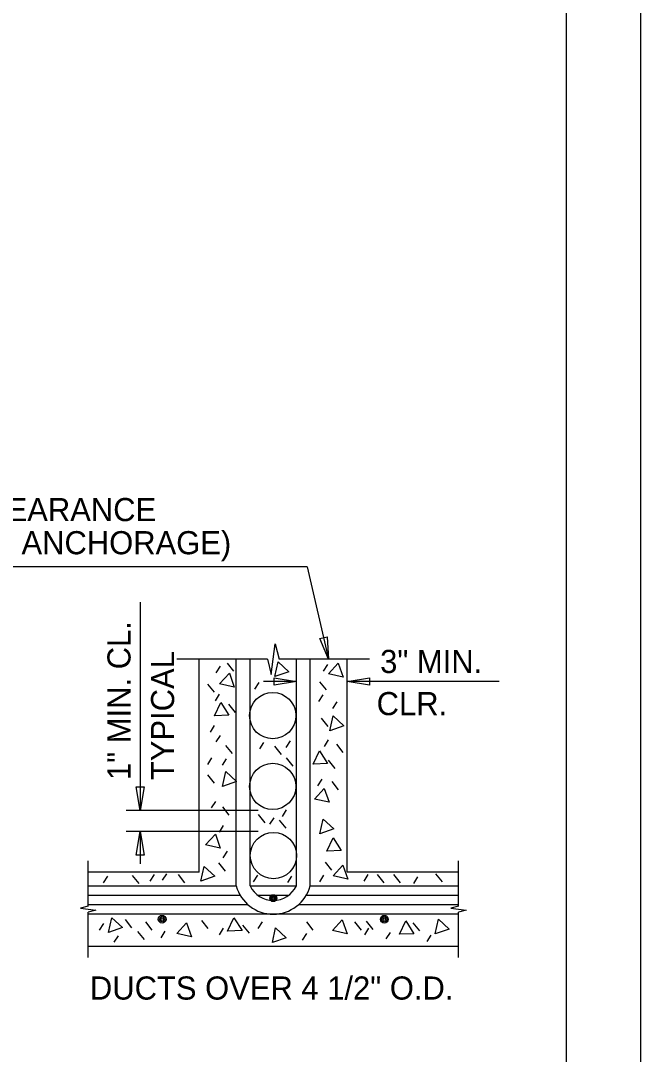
# Model space of a CAD drawing. Extents: x 0 to 22.7, y 0 to 15.7.
# Drawn here: x 19.878 to 22.667, y 4.569 to 9.222 of the extents above; entities that cross this region are included whole.
import ezdxf

# ---------------------------------------------------------------- set-up
doc = ezdxf.new("R2010")
doc.units = 0
for name, color, linetype in [('BORDER_ANNO_Cutsheet', 7, 'Continuous'), ('BRDG_ANNO_Anno-Sheet', 7, 'Continuous'), ('BRDG_ANNO_General-Notes', 7, 'Continuous'), ('BRDG_BASE_Obj-Line', 7, 'Continuous'), ('BRDG_BASE_Pattern', 7, 'Continuous'), ('BRDG_BASE_Rebar', 7, 'Continuous')]:
    doc.layers.add(name, color=color, linetype=linetype)

msp = doc.modelspace()

# ---------------------------------------------------------------- linework, layer by layer
at = {"layer": 'BORDER_ANNO_Cutsheet'}
msp.add_lwpolyline([(0, 14.6667), (22.6667, 14.6667), (22.6667, 0), (0, 0)], close=True, dxfattribs=at)
at = {"layer": 'BRDG_ANNO_Anno-Sheet'}
msp.add_lwpolyline([(1, 14.3333), (22.3333, 14.3333), (22.3333, 0.3333), (1, 0.3333)], close=True, dxfattribs=at)
at = {"layer": 'BRDG_ANNO_General-Notes'}
for p, q in [((21.1678, 6.7635), (16.9843, 6.7635)), ((21.1678, 6.7635), (21.2628, 6.348)), ((20.4157, 6.6052), (20.4157, 5.6672)), ((21.2242, 6.4418), (21.2567, 6.4492)), ((21.2628, 6.348), (21.2242, 6.4418)), ((21.2567, 6.4492), (21.2628, 6.348)), ((21.1185, 6.2471), (20.9705, 6.2471)), ((21.0185, 6.2305), (21.0185, 6.2638)), ((21.0185, 6.2638), (21.1185, 6.2471)), ((21.1185, 6.2471), (21.0185, 6.2305)), ((21.3477, 6.2471), (21.4477, 6.2638)), ((22.0306, 6.2471), (21.3477, 6.2471)), ((21.4477, 6.2305), (21.3477, 6.2471)), ((21.4477, 6.2638), (21.4477, 6.2305)), ((20.3979, 5.7739), (20.4334, 5.7739)), ((20.4157, 5.6672), (20.3979, 5.7739)), ((20.4334, 5.7739), (20.4157, 5.6672)), ((20.9471, 5.6672), (20.353, 5.6672)), ((20.9471, 5.5727), (20.353, 5.5727)), ((20.3979, 5.466), (20.4157, 5.5727)), ((20.4157, 5.5727), (20.4157, 5.4267)), ((20.4157, 5.5727), (20.4334, 5.466)), ((20.4334, 5.466), (20.3979, 5.466))]:
    msp.add_line(p, q, dxfattribs=at)
at = {"layer": 'BRDG_BASE_Obj-Line'}
for p, q in [((21.0057, 6.2786), (21.023, 6.4175)), ((21.023, 6.4175), (21.0404, 6.348)), ((20.9883, 6.348), (20.5803, 6.348)), ((20.681, 5.3897), (20.681, 6.348)), ((20.9883, 6.348), (21.0057, 6.2786)), ((21.4484, 6.348), (21.0404, 6.348)), ((21.3477, 5.3897), (21.3477, 6.348)), ((21.3496, 6.2455), (21.3477, 6.2455)), ((20.181, 5.236), (20.181, 5.4401)), ((21.8477, 5.236), (21.8477, 5.4401)), ((20.681, 5.3897), (20.181, 5.3897)), ((21.8477, 5.3897), (21.3477, 5.3897)), ((20.181, 5.236), (20.1463, 5.2274)), ((20.1463, 5.2274), (20.2157, 5.2187)), ((20.2157, 5.2187), (20.181, 5.21)), ((21.8477, 5.236), (21.813, 5.2274)), ((21.813, 5.2274), (21.8824, 5.2187)), ((21.8824, 5.2187), (21.8477, 5.21)), ((20.181, 5.006), (20.181, 5.21)), ((21.8477, 5.006), (21.8477, 5.21)), ((20.181, 5.0564), (21.8477, 5.0564))]:
    msp.add_line(p, q, dxfattribs=at)
for centre in [(21.0119, 6.0939), (21.0119, 5.7755), (21.0154, 5.4639)]:
    msp.add_circle(centre, 0.1042, dxfattribs=at)
at = {"layer": 'BRDG_BASE_Pattern'}
for p, q in [((20.8066, 6.3308), (20.8361, 6.294)), ((20.7752, 6.3168), (20.7566, 6.2872)), ((21.2583, 6.3237), (21.2396, 6.2943)), ((20.7191, 6.2363), (20.7486, 6.1994)), ((20.9492, 6.2429), (20.9306, 6.2133)), ((21.2232, 6.2468), (21.2527, 6.2099)), ((20.7717, 6.1907), (20.7531, 6.1612)), ((20.8136, 6.1453), (20.8432, 6.1084)), ((21.2372, 6.1873), (21.2187, 6.1577)), ((21.3003, 6.1557), (21.2816, 6.1262)), ((20.7486, 6.0496), (20.7301, 6.0201)), ((21.2302, 6.0823), (21.2596, 6.0454)), ((20.7752, 6.0052), (20.7566, 5.9757)), ((20.7996, 5.9598), (20.8291, 5.9229)), ((20.9712, 5.9737), (20.9527, 5.9442)), ((21.0201, 5.9562), (21.0496, 5.9194)), ((21.0903, 5.9807), (21.0716, 5.9512)), ((21.2617, 5.9843), (21.2432, 5.9547)), ((21.2984, 5.9656), (21.3279, 5.9287)), ((20.7367, 5.9037), (20.7181, 5.8742)), ((20.8032, 5.9002), (20.7846, 5.8707)), ((21.0726, 5.9037), (21.1021, 5.8669)), ((21.2616, 5.8932), (21.2912, 5.8564)), ((20.7191, 5.8268), (20.7486, 5.7899)), ((21.2328, 5.8075), (21.2141, 5.778)), ((21.2778, 5.7969), (21.3072, 5.76)), ((20.7542, 5.7077), (20.7356, 5.6782)), ((20.7856, 5.6832), (20.8152, 5.6464)), ((20.9466, 5.6482), (20.9761, 5.6114)), ((21.0167, 5.6342), (20.9982, 5.6047)), ((21.0728, 5.6692), (21.0541, 5.6397)), ((20.7892, 5.5992), (20.7706, 5.5697)), ((21.0411, 5.6236), (21.0707, 5.5868)), ((20.8067, 5.4836), (20.7881, 5.4542)), ((20.7681, 5.4312), (20.7977, 5.3944)), ((21.2477, 5.4347), (21.2771, 5.3978)), ((20.2677, 5.3713), (20.2491, 5.3418)), ((20.3795, 5.3745), (20.4091, 5.3376)), ((20.4777, 5.3786), (20.4591, 5.3492)), ((20.5337, 5.3822), (20.5151, 5.3526)), ((20.5861, 5.3788), (20.6156, 5.3419)), ((20.9432, 5.3752), (20.9246, 5.3456)), ((21.0972, 5.3717), (21.0786, 5.3422)), ((21.2408, 5.3752), (21.2221, 5.3456)), ((21.4403, 5.3786), (21.4217, 5.3492)), ((21.4821, 5.3788), (21.5117, 5.3419)), ((21.5557, 5.3788), (21.5852, 5.3419)), ((21.6643, 5.3682), (21.6457, 5.3386)), ((21.7446, 5.3822), (21.7742, 5.3453)), ((20.3472, 5.1757), (20.3767, 5.1389)), ((20.4391, 5.1652), (20.4686, 5.1283)), ((20.6911, 5.1722), (20.7206, 5.1353)), ((20.9642, 5.1652), (20.9457, 5.1356)), ((21.1636, 5.1652), (21.1932, 5.1283)), ((21.3807, 5.1652), (21.4102, 5.1283)), ((21.4332, 5.1686), (21.4627, 5.1318)), ((20.2502, 5.1581), (20.2316, 5.1286)), ((20.404, 5.1225), (20.4336, 5.0856)), ((20.5267, 5.1231), (20.5081, 5.0936)), ((20.7892, 5.1372), (20.7706, 5.1076)), ((20.8766, 5.1511), (20.9061, 5.1143)), ((21.4438, 5.1372), (21.4252, 5.1076)), ((21.5402, 5.1182), (21.5216, 5.0888)), ((21.6432, 5.1617), (21.6727, 5.1248)), ((20.3159, 5.1031), (20.2973, 5.0736)), ((21.1637, 5.1127), (21.1452, 5.0831)), ((21.7244, 5.1061), (21.7058, 5.0766))]:
    msp.add_line(p, q, dxfattribs=at)
for points in [[(21.0363, 6.3357), (21.0843, 6.2915), (21.0216, 6.2694)], [(21.2629, 6.2822), (21.3072, 6.3302), (21.3293, 6.2675)], [(20.7729, 6.2367), (20.8172, 6.2847), (20.8392, 6.222)], [(20.8146, 6.0958), (20.7493, 6.0932), (20.7781, 6.1532)], [(21.2841, 6.0924), (21.3321, 6.0481), (21.2694, 6.026)], [(21.2591, 5.8788), (21.1939, 5.8761), (21.2227, 5.9362)], [(20.8011, 5.842), (20.849, 5.7978), (20.7863, 5.7757)], [(21.1998, 5.7186), (21.2442, 5.7667), (21.2663, 5.704)], [(21.2386, 5.6285), (21.2866, 5.5843), (21.2239, 5.5622)], [(20.7098, 5.5122), (20.7542, 5.5602), (20.7762, 5.4974)], [(21.3208, 5.4868), (21.2555, 5.4842), (21.2843, 5.5442)], [(20.7031, 5.4149), (20.751, 5.3707), (20.6883, 5.3486)], [(21.2839, 5.3722), (21.3283, 5.4202), (21.3503, 5.3574)], [(20.2877, 5.1845), (20.3357, 5.1403), (20.273, 5.1182)], [(20.8741, 5.1262), (20.8089, 5.1236), (20.8377, 5.1836)], [(21.2804, 5.1271), (21.3247, 5.1751), (21.3468, 5.1124)], [(21.6477, 5.1122), (21.5824, 5.1096), (21.6112, 5.1697)], [(21.7577, 5.1777), (21.8057, 5.1335), (21.743, 5.1115)], [(20.5804, 5.1131), (20.6247, 5.1611), (20.6467, 5.0983)], [(21.0251, 5.1384), (21.0731, 5.0942), (21.0104, 5.0721)]]:
    msp.add_lwpolyline(points, close=True, dxfattribs=at)
at = {"layer": 'BRDG_BASE_Rebar'}
for p, q in [((20.8477, 5.3272), (20.8477, 6.348)), ((20.9102, 5.3272), (20.9102, 6.348)), ((21.1185, 5.3272), (21.1185, 6.348)), ((21.181, 5.3272), (21.181, 6.348)), ((20.181, 5.3272), (20.8477, 5.3272)), ((20.9102, 5.3272), (21.1185, 5.3272)), ((21.181, 5.3272), (21.8477, 5.3272)), ((20.181, 5.2855), (20.8656, 5.2855)), ((20.9451, 5.2855), (21.0842, 5.2855)), ((21.164, 5.2855), (21.8477, 5.2855)), ((20.181, 5.2439), (20.8991, 5.2439)), ((21.1296, 5.2439), (21.8477, 5.2439)), ((20.181, 5.2022), (21.8477, 5.2022))]:
    msp.add_line(p, q, dxfattribs=at)
for centre, radius in [((21.0143, 5.2723), 0.0156), ((21.0141, 5.2723), 0.0149), ((21.0141, 5.2723), 0.0149), ((21.0141, 5.2723), 0.0149), ((21.0138, 5.2724), 0.0141), ((21.0138, 5.2724), 0.0141), ((21.0138, 5.2724), 0.0141), ((21.0136, 5.2725), 0.0134), ((21.0143, 5.2723), 0.0104), ((21.0141, 5.2723), 0.00991), ((21.0141, 5.2723), 0.00991), ((21.0141, 5.2723), 0.00991), ((21.0138, 5.2724), 0.00941), ((21.0138, 5.2724), 0.00941), ((21.0138, 5.2724), 0.00941), ((21.0136, 5.2725), 0.00894), ((21.0143, 5.2723), 0.00522), ((21.0141, 5.2723), 0.00495), ((21.0141, 5.2723), 0.00495), ((21.0141, 5.2723), 0.00495), ((21.0138, 5.2724), 0.00471), ((21.0138, 5.2724), 0.00471), ((21.0138, 5.2724), 0.00471), ((21.0136, 5.2725), 0.00447), ((20.5144, 5.1777), 0.0173), ((20.5144, 5.1777), 0.0116), ((20.5144, 5.1777), 0.00578), ((21.5144, 5.1777), 0.0173), ((21.5144, 5.1777), 0.0116), ((21.5144, 5.1777), 0.00578)]:
    msp.add_circle(centre, radius, dxfattribs=at)
for centre, radius, start, end in [((21.0143, 5.373), 0.1728, 195.3683, 344.6317), ((21.0143, 5.3788), 0.1163, 206.3608, 333.6392)]:
    msp.add_arc(centre, radius, start, end, dxfattribs=at)

# ---------------------------------------------------------------- texts
at = {"layer": 'BRDG_ANNO_General-Notes'}
for s, height, p in [('3" MINIMUM AND 4" MAXIMUM CLEARANCE', 0.104115, (17.5961, 6.9694)), ('(EXCEPT 2" MINIMUM CLEARANCE NEAR ANCHORAGE)', 0.104115, (17.0935, 6.8203)), ('3" MIN.', 0.10413, (21.4956, 6.2857)), ('CLR.', 0.10417, (21.4798, 6.096))]:
    msp.add_text(s, height=height, dxfattribs=at).set_placement(p)
for s, height, rotation, p in [('1" MIN. CL.', 0.104167, 90, (20.3721, 5.804)), ('TYPICAL', 0.10417, 90, (20.5684, 5.8037)), ('DUCTS OVER 4 1/2" O.D.', 0.104167, 360, (20.1892, 4.8158))]:
    msp.add_text(s, height=height, rotation=rotation, dxfattribs=at).set_placement(p)

doc.saveas('drawing.dxf')
